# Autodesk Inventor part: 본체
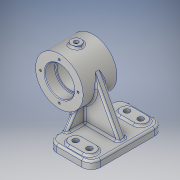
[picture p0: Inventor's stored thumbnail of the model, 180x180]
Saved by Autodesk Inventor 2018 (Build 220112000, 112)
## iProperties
Created: 2023-08
Part Number: 본체
Material: 알루미늄 6061
Document SubType Name: Modeling
Designer: home
Density: 2.7 g/cm^3
Appearance: 알루미늄 - 평지
Mass: 777.806 g
Surface Area: 536.477 cm^2
Volume: 288.076 cm^3
Author: home
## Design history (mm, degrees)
sketch "스케치1"
  geometry: C1 r 38 at (0, 0); 1 further point
  constraints: 1 centre point, 1 coincident
  dimensions: "d0" = 76 diameter of C1
extrude "돌출1" new body sketch "스케치1" stored distance "d1" = 54; taper "d2" = 0 deg
sketch "스케치3"
  geometry: C1 r 38 at (0, 0) reference; 2 further points
  constraints: 1 vertical alignment
  dimensions: "d8" = 30 distance of point (0, 0) point (0, 30)
hole "구멍1" sketch "스케치3" at (0, 30) diameter "d9" = 3.242; stored, may be unused: countersink angle "d13" = 90 deg, drill point angle "d15" = 118 deg; dims "d10" = 8, "d11" = 4, "d12" = 2, "d14" = 10
sketch "스케치4"
  geometry: L1 (12, -58)-(82, -58); L2 (82, -58)-(82, -70); L3 (82, -70)-(12, -70); L4 (12, -70)-(12, -58); C1 r 38 at (0, 0) reference; 1 further point
  constraints: 8 end point, 2 parallel, 1 horizontal, 1 perpendicular
  dimensions: "d19" = 70 distance from line of L3 point (0, 0); "d20" = 82 distance from line of L2 C1.centre; "d21" = 70 distance of L2.end L3.end; "d22" = 12 distance of L1.end L2.end
extrude "돌출2" join sketch "스케치4" stored distance "d23" = 116; taper "d24" = 0 deg
sketch "스케치5"
  geometry: L1 (0, 22)-(8, 22); L2 (8, 22)-(8, 94); L3 (8, 94)-(0, 94); L4 (0, 94)-(0, 22); L5 (0, 22)-(8, 94); L6 (8, 22)-(0, 94); L7 (0, 0)-(0, 116) reference; L8 (0, 0)-(70, 0) reference; 4 further points
  constraints: 12 end point, 5 midpoint, 2 parallel, 1 horizontal, 1 horizontal alignment, 1 perpendicular
  dimensions: "d25" = 8 distance of L2.end L3.end; "d26" = 22 distance between parallel lines of L8 L1
node "작업 평면1"
sketch "스케치9"
  geometry: L1 (0, 64)-(62, 64); L2 (62, 64)-(62, 52); L3 (62, 52)-(0, 52); L4 (0, 52)-(0, 64); L5 (0, 64)-(62, 52); L6 (62, 64)-(0, 52); L7 (70, 0)-(70, 116) reference; L8 (0, 0)-(0, 116) reference; 4 further points
  constraints: 12 end point, 5 midpoint, 2 parallel, 1 horizontal, 1 horizontal alignment, 1 perpendicular
  dimensions: "d41" = 12 distance of L1.end L2.end; "d42" = 8 distance between parallel lines of L7 L2
fillet "모깎기1" dims "d51" = 15
sketch "스케치11"
  geometry: L1 (33.529, 17.882)-(74, -58); L2 (82, -58)-(82, -70) reference; L3 (67, -58)-(82, -58) reference; L4 (12, -70)-(12, -58) reference; L5 (12, -58)-(12, -36.056); L6 (82, -58)-(82, -70) reference; L7 (82, -70)-(12, -70) reference; L8 (12, -70)-(12, -58) reference; L9 (12, -58)-(82, -58) reference; A1 r 38 centre (0, 0) between (33.529, 17.882) and (12, -36.056) reference; A2 r 38 centre (0, 0) between (33.529, 17.882) and (12, -36.056) reference; 1 further point
  constraints: 4 end point, 2 point on circle, 1 collinear, 1 point on line, 1 tangent
  dimensions: "d53" = 8 distance from line of L2 L1.end
extrude "돌출3" join sketch "스케치11" stored distance "d54" = 12; taper "d55" = 0 deg
sketch "스케치13"
  geometry: L1 (-15, 94)-(-7, 94); L2 (-7, 94)-(-7, 22); L3 (-7, 22)-(-15, 22); L4 (-15, 22)-(-15, 94); L5 (-15, 94)-(-7, 22); L6 (-7, 94)-(-15, 22); L7 (0, 0)-(40, 0) reference; L8 (-15, 15)-(-15, 101) reference; 3 further points
  constraints: 12 end point, 3 midpoint, 2 parallel, 1 horizontal, 1 horizontal alignment, 1 perpendicular
  dimensions: "d57" = 8 distance of L2.end L3.end; "d58" = 22 distance between parallel lines of L7 L3; "d59" = 0 distance between parallel lines of L8 L4
sketch "스케치14"
  geometry: L1 (7, 12)-(31.942, 50.408); L2 (52.675, 52.536)-(79, 12); L3 (101, 0)-(101, 12) reference; L4 (-15, 12)-(-15, 0) reference; L5 (86, 12)-(101, 12) reference; L6 (-15, 12)-(0, 12) reference; L7 (31.942, 50.408)-(52.675, 52.536); L8 (16, 33.944)-(16, 106.056) reference; L9 (16, 106.056)-(70, 106.056) reference; L10 (70, 106.056)-(70, 33.944) reference; L11 (70, 33.944)-(49, 33.944) reference; L12 (49, 33.944)-(37, 33.944) reference; L13 (37, 33.944)-(16, 33.944) reference; L14 (49, 33.944)-(49, 12) reference; L15 (49, 12)-(86, 12) reference; L16 (86, 12)-(86, 0) reference; L17 (86, 0)-(0, 0) reference; L18 (0, 0)-(0, 12) reference; L19 (0, 12)-(37, 12) reference; L20 (37, 12)-(37, 33.944) reference; 1 further point
  constraints: 6 end point, 2 point on line
  dimensions: "d60" = 22 distance from line of L3 L2.end; "d61" = 22 distance from line of L4 L1.start; "d62" = 123 deg angle of L5 L2; "d63" = 123 deg angle of L6 L1
extrude "돌출4" join sketch "스케치14" distance "d64" = 8; taper "d65" = 0 deg
fillet "모깎기3" dims "d66" = 3
fillet "모깎기4" dims "d67" = 3
sketch "스케치15"
  geometry: L1 (0, 27)-(0, -27); L2 (-38, -27)-(38, -27) reference; L3 (38, 27)-(-38, 27) reference; L4 (23.5, 27)-(23.5, 11); L5 (22.5, 10)-(20.5, 10); L6 (20.5, 10)-(20.5, -10); L7 (20.5, -10)-(22.5, -10); L8 (23.5, -11)-(23.5, -27); A1 r 1 centre (22.5, 11) between (22.5, 10) and (23.5, 11); A2 r 1 centre (22.5, -11) between (23.5, -11) and (22.5, -10); 3 further points
  constraints: 12 end point, 6 point on line, 4 point on circle, 4 tangent, 3 perpendicular, 2 centre point, 2 midpoint, 2 vertical, 1 coincident, 1 collinear, 1 equal radius
  dimensions: "d68" = 47 diameter of L8 L1; "d69" = 41 diameter of L6 L1; "d70" = 17 distance of point (23.5, -10) L8.end; "d71" = 1 radius of A1
revolve "회전2" sketch "스케치15" stored, may be unused: angle "d72" = 90 deg
sketch "스케치16"
  geometry: L1 (17, -50)-(39, -50); L2 (17, -60)-(39, -60); L3 (39, -40)-(17, -40); L4 (-6, 28.629)-(-8, 28.629) reference; L5 (0, 0)-(0, 21.475) reference; L6 (46, 0)-(0, 0) reference; L7 (52.8, -12)-(52.8, -6) reference; L8 (0, -18)-(46, -18) reference; L9 (0, -39.475)-(0, -18) reference; L10 (-8, -46.629)-(-6, -46.629) reference; L11 (-11, -41.423)-(-11, 23.423) reference; L12 (-8, 34)-(-8, 28.629) reference; L13 (4, 46)-(44, 46) reference; L14 (56, -52)-(56, 34) reference; L15 (44, -64)-(4, -64) reference; L16 (-8, -46.629)-(-8, -52) reference; L17 (59, -52)-(59, 34) reference; A1 r 10 centre (17, -50) between (17, -40) and (17, -60); A2 r 10 centre (39, -50) between (39, -60) and (39, -40); A3 r 12 centre (4, 34) between (4, 46) and (-8, 34) reference; A4 r 12 centre (44, 34) between (56, 34) and (44, 46) reference; A5 r 12 centre (44, -52) between (44, -64) and (56, -52) reference; A6 r 12 centre (4, -52) between (-8, -52) and (4, -64) reference; 6 further points; 2 other entities
  constraints: 8 end point, 4 point on circle, 4 tangent, 2 centre point, 1 horizontal, 1 midpoint, 1 parallel, 8 other
  dimensions: "d84" = 20 distance between parallel lines of L3 L2; "d85" = 41 distance from line of point (-23, -9) L1; "d105" = 22 distance of L1.start L1.end; "d106" = 20 distance from line of L17 L1.end
extrude "돌출5" join sketch "스케치16" distance "d75" = 3; taper "d76" = 0 deg
sketch "스케치17"
  geometry: L1 (17, -40)-(39, -40) reference; L2 (39, -60)-(17, -60) reference; L3 (-11, -39.475)-(-11, 21.475) reference; L4 (-8, 25.052)-(-6, 25.052) reference; L5 (-3, 21.475)-(-3, 0) reference; L6 (0, -3)-(46, -3) reference; L7 (49.4, -6)-(49.4, -12) reference; L8 (46, -15)-(0, -15) reference; L9 (-3, -18)-(-3, -39.475) reference; L10 (-6, -43.052)-(-8, -43.052) reference; A1 r 10 centre (17, -50) between (17, -40) and (17, -60) reference; A2 r 10 centre (39, -50) between (39, -60) and (39, -40) reference; A3 r 3 centre (0, 0) between (-3, 0) and (0, -3) reference; A4 r 3 centre (0, -18) between (0, -15) and (-3, -18) reference; 7 further points; 6 other entities
  constraints: 6 other
hole "구멍2" sketch "스케치17" at (39, -50), (17, -50) diameter "d77" = 9; stored, may be unused: countersink angle "d81" = 90 deg, drill point angle "d83" = 118 deg; dims "d78" = 8, "d79" = 4, "d80" = 2, "d82" = 10
fillet "모깎기5" dims "d86" = 3
sketch "스케치18"
  geometry: L1 (86, 0)-(0, 0) reference; 2 further points
  constraints: 1 vertical alignment, 1 other
  dimensions: "d87" = 19 distance from line of L1 point (43, 19)
feature "엠보싱1" sketch "스케치18" dims "d2" = 0, "d20" = 82, "d88" = 0.5, "d89" = 0
node "작업 평면2"
sketch "스케치19"
  geometry: C1 r 8 at (27, 58); 1 further point
  constraints: 1 centre point, 1 coincident
  dimensions: "d91" = 16 diameter of C1
extrude "돌출6" join sketch "스케치19" distance "d92" = 7.25; taper "d93" = 0 deg
sketch "스케치20"
  geometry: C1 r 8 at (0, 0) reference; 1 further point
hole "구멍3" sketch "스케치20" at (0, 0) diameter "d94" = 5.188; stored, may be unused: countersink angle "d98" = 90 deg, drill point angle "d100" = 118 deg; dims "d95" = 43, "d96" = 7, "d97" = 4, "d99" = 43
fillet "모깎기6" dims "d101" = 3
chamfer "모따기1" distance "d102" = 1; stored, may be unused: second distance "d103" = 2, angle "d104" = 45 deg
node "솔리드1"
pattern_circular "원형 패턴1" dims angle "d17" = 360 deg
mirror "미러1"
mirror "미러2"
node "절단 모서리 투영3"
node "절단 모서리 투영4"
node "절단 모서리 투영5"
node "절단 모서리 투영6"
node "절단 모서리 투영7"
other parameters: "d90" = -111
